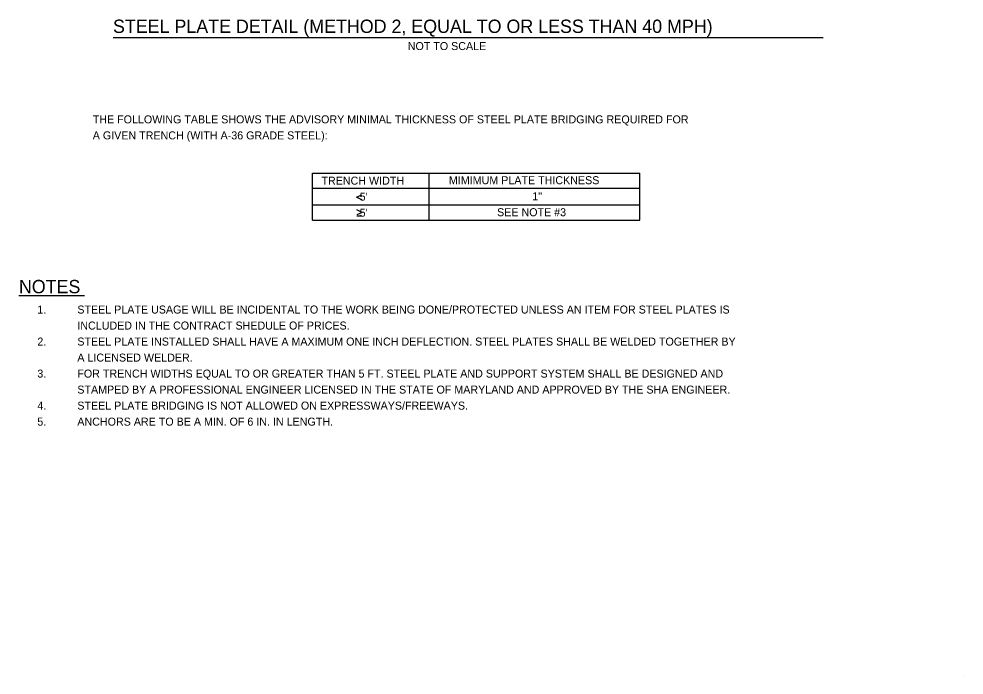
# Model space of a CAD drawing. Extents: x 12.5 to 19.6, y 6 to 16.
# Drawn here: x 12.53 to 19.62, y 5.98 to 10.9 of the extents above; entities that cross this region are included whole.
import ezdxf

# ---------------------------------------------------------------- set-up
doc = ezdxf.new("R2010")
doc.units = 0
for name, color, linetype in [('Default', 7, 'Continuous'), ('DETL-NOTE', 7, 'Continuous'), ('TTLB-TEXT', 7, 'Continuous')]:
    doc.layers.add(name, color=color, linetype=linetype)

msp = doc.modelspace()

# ---------------------------------------------------------------- linework, layer by layer
at = {"layer": 'Default'}
msp.add_line((13.2417, 10.7615), (18.564, 10.7615), dxfattribs=at)
at = {"layer": 'DETL-NOTE'}
for p, q in [((14.7358, 9.7451), (17.1887, 9.7451)), ((14.7358, 9.3947), (14.7358, 9.7451)), ((15.6107, 9.3947), (15.6107, 9.7451)), ((17.1887, 9.3947), (17.1887, 9.7451)), ((14.7358, 9.6327), (17.1887, 9.6327)), ((15.0654, 9.5661), (15.1053, 9.5847)), ((14.7358, 9.509), (17.1887, 9.509)), ((15.0654, 9.5661), (15.1053, 9.5475)), ((15.1077, 9.4522), (15.0677, 9.4708)), ((15.1077, 9.4522), (15.0677, 9.4336)), ((15.0677, 9.4261), (15.1077, 9.4261)), ((14.7358, 9.3947), (17.1887, 9.3947)), ((12.5344, 8.8289), (13.0253, 8.8289))]:
    msp.add_line(p, q, dxfattribs=at)
at = {"layer": 'TTLB-TEXT'}
msp.add_line((19.6208, 5.9844), (19.6208, 5.9844), dxfattribs=at)

# ---------------------------------------------------------------- texts
at = {"layer": 'Default'}
for s, height, p in [('STEEL PLATE DETAIL (METHOD 2, EQUAL TO OR LESS THAN 40 MPH)', 0.1, (13.2399, 10.7967)), ('NOT TO SCALE', 0.06, (15.4496, 10.6685))]:
    msp.add_text(s, height=height, dxfattribs=at).set_placement(p)
at = {"layer": 'DETL-NOTE'}
for s, height, p in [('THE FOLLOWING TABLE SHOWS THE ADVISORY MINIMAL THICKNESS OF STEEL PLATE BRIDGING REQUIRED FOR', 0.06, (13.0881, 10.1191)), ('A GIVEN TRENCH (WITH A-36 GRADE STEEL):', 0.06, (13.0881, 9.9991)), ('TRENCH WIDTH', 0.06, (14.8026, 9.6598)), ('MIMIMUM PLATE THICKNESS', 0.06, (15.7583, 9.6632)), ("  5'", 0.06, (15.0446, 9.5398)), ('1"', 0.06, (16.3836, 9.5432)), ("  5'", 0.06, (15.0446, 9.4198)), ('SEE NOTE #3', 0.06, (16.1194, 9.4232)), ('NOTES', 0.1, (12.5344, 8.846)), ('1.', 0.06, (12.6724, 8.6939)), ('STEEL PLATE USAGE WILL BE INCIDENTAL TO THE WORK BEING DONE/PROTECTED UNLESS AN ITEM FOR STEEL PLATES IS ', 0.06, (12.9724, 8.6939)), ('INCLUDED IN THE CONTRACT SHEDULE OF PRICES.', 0.06, (12.9724, 8.5739)), ('2.', 0.06, (12.6724, 8.4539)), ('STEEL PLATE INSTALLED SHALL HAVE A MAXIMUM ONE INCH DEFLECTION. STEEL PLATES SHALL BE WELDED TOGETHER BY ', 0.06, (12.9724, 8.4539)), ('A LICENSED WELDER.', 0.06, (12.9724, 8.3339)), ('3.', 0.06, (12.6724, 8.2139)), ('FOR TRENCH WIDTHS EQUAL TO OR GREATER THAN 5 FT. STEEL PLATE AND SUPPORT SYSTEM SHALL BE DESIGNED AND ', 0.06, (12.9724, 8.2139)), ('STAMPED BY A PROFESSIONAL ENGINEER LICENSED IN THE STATE OF MARYLAND AND APPROVED BY THE SHA ENGINEER.', 0.06, (12.9724, 8.0939)), ('4.', 0.06, (12.6724, 7.9739)), ('STEEL PLATE BRIDGING IS NOT ALLOWED ON EXPRESSWAYS/FREEWAYS.', 0.06, (12.9724, 7.9739)), ('5.', 0.06, (12.6724, 7.8539)), ('ANCHORS ARE TO BE A MIN. OF 6 IN. IN LENGTH.', 0.06, (12.9724, 7.8539))]:
    msp.add_text(s, height=height, dxfattribs=at).set_placement(p)

doc.saveas('drawing.dxf')
